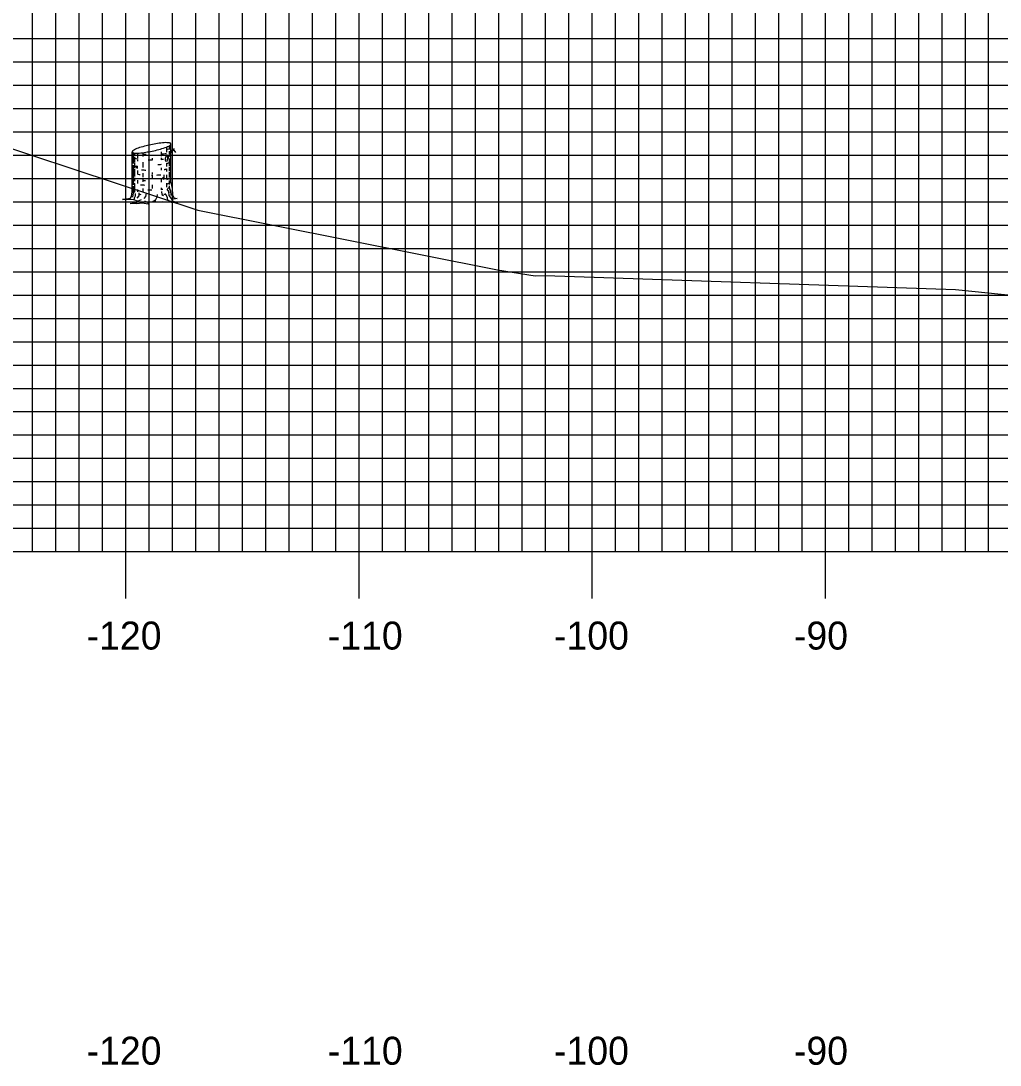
# Model space of a CAD drawing. Extents: x 857504 to 857847, y 364765 to 364985.
# Drawn here: x 857544.81 to 857586.8, y 364896.29 to 364941.06 of the extents above; entities that cross this region are included whole.
import ezdxf

# ---------------------------------------------------------------- set-up
doc = ezdxf.new("R2010")
doc.units = 0
for name, color, linetype in [('H_V ANNOTATION', 7, 'Continuous'), ('M_Trees_Conifer_Pay', 7, 'Continuous'), ('MAJOR', 7, 'Continuous'), ('MINOR', 7, 'Continuous'), ('S_Roadway_Centerline', 7, 'Continuous')]:
    doc.layers.add(name, color=color, linetype=linetype)

msp = doc.modelspace()

# ---------------------------------------------------------------- linework, layer by layer
at = {"layer": 'M_Trees_Conifer_Pay'}
for p, q in [((857551.056, 364935.645), (857551.056, 364935.422)), ((857551.173, 364935.706), (857551.173, 364935.544)), ((857551.245, 364934.132), (857551.245, 364935.779)), ((857549.58, 364933.721), (857549.58, 364935.443)), ((857549.628, 364935.406), (857549.628, 364934.935)), ((857549.686, 364935.395), (857549.686, 364935.297)), ((857549.686, 364935.223), (857549.686, 364935.019)), ((857549.811, 364935.387), (857549.811, 364935.155)), ((857550.031, 364935.407), (857550.031, 364935.239)), ((857550.827, 364935.449), (857550.827, 364935.25)), ((857550.827, 364935.192), (857550.827, 364935.103)), ((857551.056, 364935.334), (857551.056, 364935.286)), ((857551.173, 364935.476), (857551.173, 364935.348)), ((857549.628, 364934.87), (857549.628, 364934.562)), ((857549.686, 364934.961), (857549.686, 364934.761)), ((857549.811, 364935.114), (857549.811, 364935.04)), ((857550.031, 364935.002), (857550.031, 364934.765)), ((857550.437, 364935.176), (857550.437, 364935.08)), ((857550.827, 364934.756), (857550.827, 364934.651)), ((857551.056, 364934.951), (857551.056, 364934.819)), ((857551.113, 364935.151), (857551.061, 364935.091)), ((857551.173, 364935.161), (857551.173, 364934.825)), ((857551.173, 364934.788), (857551.173, 364934.626)), ((857549.628, 364934.515), (857549.628, 364934.023)), ((857549.686, 364934.714), (857549.686, 364934.378)), ((857549.686, 364934.325), (857549.686, 364934.189)), ((857549.811, 364934.636), (857549.811, 364934.498)), ((857550.031, 364934.521), (857550.031, 364934.368)), ((857550.031, 364934.325), (857550.031, 364934.152)), ((857550.437, 364934.562), (857550.437, 364934.488)), ((857550.437, 364934.463), (857550.437, 364934.315)), ((857551.056, 364934.708), (857551.056, 364934.599)), ((857551.056, 364934.463), (857551.056, 364934.321)), ((857551.173, 364934.578), (857551.173, 364934.362)), ((857551.173, 364934.331), (857551.173, 364934.257)), ((857549.628, 364933.969), (857549.628, 364933.721)), ((857549.686, 364934.09), (857549.686, 364933.712)), ((857549.811, 364934.226), (857549.811, 364934.084)), ((857550.031, 364933.874), (857550.031, 364933.721)), ((857550.437, 364934.023), (857550.437, 364933.87)), ((857550.827, 364934.284), (857550.827, 364934.137)), ((857550.827, 364933.905), (857550.827, 364933.817)), ((857551.056, 364934.094), (857551.056, 364933.922)), ((857551.173, 364934.216), (857551.173, 364934.043)), ((857549.811, 364933.822), (857549.811, 364933.728)), ((857549.811, 364933.328), (857549.974, 364933.392)), ((857550.248, 364933.264), (857550.122, 364933.328))]:
    msp.add_line(p, q, dxfattribs=at)
for points in [[(857551.028, 364935.239), (857550.997, 364935.155), (857550.993, 364935.087), (857551.024, 364935.023)], [(857551.061, 364935.277), (857551.098, 364935.202), (857551.145, 364935.259), (857551.203, 364935.328), (857551.296, 364935.521), (857551.36, 364935.569), (857551.391, 364935.575)], [(857551.076, 364935.023), (857551.113, 364935.151), (857551.176, 364935.266), (857551.207, 364935.334), (857551.276, 364935.48)], [(857551.29, 364935.509), (857551.366, 364935.517), (857551.438, 364935.418)], [(857549.76, 364934.749), (857549.754, 364934.844), (857549.797, 364934.821), (857549.797, 364934.727)], [(857550.899, 364934.35), (857550.911, 364934.273), (857550.958, 364934.284), (857550.946, 364934.45)], [(857551.245, 364934.132), (857551.296, 364933.87), (857551.312, 364933.596), (857551.37, 364933.471), (857551.506, 364933.44), (857551.275, 364933.403), (857551.275, 364933.403), (857551.281, 364933.355), (857551.529, 364933.261), (857551.254, 364933.277), (857550.899, 364933.298), (857550.577, 364933.287), (857550.584, 364933.37), (857550.435, 364933.287), (857550.248, 364933.264), (857550.273, 364933.197), (857550.005, 364933.24), (857549.785, 364933.213), (857549.492, 364933.23), (857549.781, 364933.287), (857549.811, 364933.328), (857549.649, 364933.386), (857549.412, 364933.397), (857549.171, 364933.397), (857549.513, 364933.454), (857549.554, 364933.534), (857549.58, 364933.721)], [(857551.071, 364933.843), (857551.145, 364933.738), (857551.15, 364933.565), (857551.275, 364933.403)], [(857551.17, 364933.989), (857551.176, 364933.843), (857551.224, 364933.775), (857551.234, 364933.576)], [(857549.628, 364933.674), (857549.607, 364933.596), (857549.587, 364933.502)], [(857549.706, 364933.654), (857549.712, 364933.538), (857549.659, 364933.45), (857549.649, 364933.386)], [(857549.869, 364933.681), (857549.869, 364933.549), (857549.781, 364933.45)], [(857550.096, 364933.44), (857550.163, 364933.534), (857550.19, 364933.674)], [(857550.584, 364933.37), (857550.658, 364933.511), (857550.668, 364933.613)], [(857550.834, 364933.738), (857550.845, 364933.613), (857550.919, 364933.569)], [(857551.113, 364933.349), (857551.098, 364933.487), (857551.024, 364933.616)]]:
    msp.add_lwpolyline(points, dxfattribs=at)
for centre, radius, start, end in [((857551.436, 364930.676), 5.179, 101.7194, 108.0594), ((857551.436, 364930.676), 5.179, 95.3794, 101.7194), ((857551.026, 364935.034), 0.802, 79.2194, 95.3794), ((857550.746, 364936.384), 0.802, 288.0594, 304.2194), ((857551.129, 364935.575), 0.251, 71.0501, 79.2194), ((857551.056, 364935.929), 0.251, 304.2194, 312.3887), ((857551.184, 364935.735), 0.0817, 56.7194, 71.0501), ((857551.169, 364935.804), 0.0817, 312.3887, 326.7194), ((857551.185, 364935.664), 0.0624, 311.2506, 330), ((857551.2, 364935.759), 0.0527, 46.923, 56.7194), ((857551.214, 364935.774), 0.0314, 34.2194, 46.923), ((857551.194, 364935.788), 0.0527, 326.7194, 336.5158), ((857551.201, 364935.655), 0.0441, 330, 343.9485), ((857551.218, 364935.777), 0.0264, 23.4074, 34.2194), ((857551.213, 364935.78), 0.0314, 336.5158, 349.2194), ((857551.222, 364935.779), 0.0226, 11.7194, 23.4074), ((857551.211, 364935.652), 0.0334, 343.9485, 354.2151), ((857551.222, 364935.779), 0.0226, 0.0315, 11.7194), ((857551.218, 364935.779), 0.0264, 349.2194, 0.0315), ((857549.613, 364935.265), 0.0334, 163.9485, 180), ((857549.613, 364935.265), 0.0334, 180, 196.0515), ((857549.612, 364935.442), 0.0314, 156.5158, 169.2194), ((857549.607, 364935.443), 0.0264, 169.2194, 180.0315), ((857549.603, 364935.443), 0.0226, 180.0315, 191.7194), ((857549.603, 364935.443), 0.0226, 191.7194, 203.4074), ((857549.623, 364935.268), 0.0441, 196.0515, 210), ((857549.607, 364935.444), 0.0264, 203.4074, 214.2194), ((857549.631, 364935.434), 0.0527, 146.7194, 156.5158), ((857549.611, 364935.447), 0.0314, 214.2194, 226.923), ((857549.639, 364935.277), 0.0624, 210, 228.7494), ((857549.656, 364935.418), 0.0817, 132.3887, 146.7194), ((857549.625, 364935.463), 0.0527, 226.923, 236.7194), ((857549.641, 364935.487), 0.0817, 236.7194, 251.0501), ((857549.711, 364935.36), 0.172, 228.7494, 240), ((857549.77, 364935.293), 0.251, 124.2194, 132.3887), ((857549.696, 364935.647), 0.251, 251.0501, 259.2194), ((857549.91, 364935.705), 0.571, 240, 240.3367), ((857550.079, 364934.837), 0.802, 108.0594, 124.2194), ((857549.799, 364936.188), 0.802, 259.2194, 275.3794), ((857549.389, 364940.546), 5.179, 275.3794, 281.7194), ((857550.413, 364939.455), 4.124, 264.6955, 266.7331), ((857549.389, 364940.546), 5.179, 281.7194, 288.0594), ((857550.413, 364939.455), 4.124, 276.238, 278.1032), ((857550.914, 364935.938), 0.571, 278.1032, 284.3667), ((857550.914, 364936.092), 0.571, 284.4317, 292.4132), ((857550.914, 364935.938), 0.571, 297.0237, 300), ((857551.113, 364935.747), 0.172, 300, 311.2506), ((857551.113, 364935.593), 0.172, 300, 311.2506), ((857551.185, 364935.51), 0.0624, 311.2506, 330), ((857551.201, 364935.501), 0.0441, 330, 343.9485), ((857551.211, 364935.498), 0.0334, 343.9485, 354.2151), ((857549.613, 364934.818), 0.0334, 163.9485, 180), ((857549.613, 364934.818), 0.0334, 180, 196.0515), ((857549.623, 364934.821), 0.0441, 196.0515, 210), ((857549.639, 364934.83), 0.0624, 210, 228.7494), ((857549.711, 364934.913), 0.172, 228.7494, 240), ((857549.91, 364935.258), 0.571, 240, 240.3367), ((857549.912, 364935.494), 0.571, 240, 247.0587), ((857549.91, 364935.705), 0.571, 246.8597, 257.9846), ((857550.411, 364939.222), 4.124, 268.0751, 270), ((857550.411, 364939.222), 4.124, 270, 270.3581), ((857550.413, 364939.011), 4.124, 273.7052, 275.9504), ((857550.411, 364939.222), 4.124, 275.7849, 277.0558), ((857550.913, 364935.494), 0.571, 284.4493, 297.0429), ((857550.912, 364935.258), 0.571, 297.1896, 300), ((857551.111, 364934.913), 0.172, 300, 311.2506), ((857551.184, 364934.83), 0.0624, 311.2506, 330), ((857551.2, 364934.821), 0.0441, 330, 343.9485), ((857551.21, 364934.818), 0.0334, 343.9485, 354.2151), ((857551.211, 364935.054), 0.0334, 343.9485, 354.2151), ((857549.613, 364934.608), 0.0334, 163.9485, 180), ((857549.613, 364934.608), 0.0334, 180, 196.0515), ((857549.613, 364934.371), 0.0334, 163.9485, 180), ((857549.613, 364934.371), 0.0334, 180, 196.0515), ((857549.623, 364934.611), 0.0441, 196.0515, 210), ((857549.623, 364934.374), 0.0441, 196.0515, 210), ((857549.639, 364934.62), 0.0624, 210, 228.7494), ((857549.639, 364934.383), 0.0624, 210, 228.7494), ((857549.711, 364934.703), 0.172, 228.7494, 240), ((857549.711, 364934.466), 0.172, 228.7494, 240), ((857549.91, 364935.048), 0.571, 240, 246.8597), ((857549.91, 364934.811), 0.571, 240, 246.8597), ((857549.91, 364935.048), 0.571, 259.2707, 261.8968), ((857550.411, 364938.565), 4.124, 261.8968, 263.1474), ((857550.411, 364938.775), 4.124, 264.081, 266.6676), ((857550.411, 364938.565), 4.124, 270, 270.3581), ((857550.411, 364938.565), 4.124, 273.1493, 275.4569), ((857550.411, 364938.775), 4.124, 277.6125, 278.1032), ((857550.912, 364935.258), 0.571, 278.1032, 286.9296), ((857550.912, 364934.811), 0.571, 285.3983, 297.1896), ((857550.912, 364935.048), 0.571, 297.1896, 300), ((857551.111, 364934.703), 0.172, 300, 311.2506), ((857551.184, 364934.62), 0.0624, 311.2506, 330), ((857551.2, 364934.611), 0.0441, 330, 343.9485), ((857551.21, 364934.608), 0.0334, 343.9485, 354.2151), ((857549.613, 364934.174), 0.0334, 163.9485, 180), ((857549.613, 364933.978), 0.0334, 163.9485, 180), ((857549.613, 364933.978), 0.0334, 180, 196.0515), ((857549.623, 364933.981), 0.0441, 196.0515, 210), ((857549.639, 364933.99), 0.0624, 210, 228.7494), ((857549.711, 364934.073), 0.172, 228.7494, 240), ((857549.9, 364934.62), 0.571, 241.2369, 248.0268), ((857549.91, 364934.418), 0.571, 240, 246.8597), ((857550.411, 364938.131), 4.124, 263.4991, 265.8397), ((857550.411, 364938.329), 4.124, 264.716, 266.3193), ((857550.411, 364937.935), 4.124, 275.7849, 276.7896), ((857550.912, 364934.418), 0.571, 288.5067, 297.2721), ((857550.912, 364934.613), 0.571, 289.2907, 300), ((857551.111, 364934.268), 0.172, 300, 311.2506), ((857551.184, 364934.186), 0.0624, 311.2506, 330), ((857551.2, 364934.177), 0.0441, 330, 343.9485), ((857551.21, 364934.174), 0.0334, 343.9485, 354.2151), ((857549.613, 364933.758), 0.0334, 163.9485, 180), ((857549.613, 364933.758), 0.0334, 180, 196.0515), ((857549.623, 364933.761), 0.0441, 196.0515, 210), ((857549.639, 364933.77), 0.0624, 210, 228.7494), ((857549.711, 364933.853), 0.172, 228.7494, 240), ((857549.91, 364934.198), 0.571, 240, 244.5314), ((857550.411, 364937.715), 4.124, 262.4438, 263.512), ((857550.411, 364937.935), 4.124, 267.8117, 270), ((857550.411, 364937.935), 4.124, 270, 270.1328), ((857550.411, 364937.715), 4.124, 277.3684, 278.1032), ((857550.912, 364934.198), 0.571, 278.1032, 281.637), ((857551.111, 364933.853), 0.172, 300, 311.2506), ((857551.184, 364933.77), 0.0624, 311.2506, 330), ((857551.2, 364933.761), 0.0441, 330, 343.9485), ((857551.21, 364933.758), 0.0334, 343.9485, 354.2151)]:
    msp.add_arc(centre, radius, start, end, dxfattribs=at)
at = {"layer": 'MAJOR'}
for p, q in [((857549.308, 364918.302), (857549.308, 364963.302)), ((857559.308, 364918.302), (857559.308, 364963.302)), ((857569.308, 364918.302), (857569.308, 364963.302)), ((857579.308, 364918.302), (857579.308, 364963.302)), ((857529.308, 364938.302), (857809.308, 364938.302)), ((857529.308, 364933.302), (857809.308, 364933.302)), ((857529.308, 364928.302), (857809.308, 364928.302)), ((857529.308, 364923.302), (857809.308, 364923.302)), ((857529.308, 364918.302), (857809.308, 364918.302)), ((857529.308, 364918.302), (857809.308, 364918.302)), ((857549.308, 364916.298), (857549.308, 364918.302)), ((857559.308, 364916.298), (857559.308, 364918.302)), ((857569.308, 364916.298), (857569.308, 364918.302)), ((857579.308, 364916.298), (857579.308, 364918.302))]:
    msp.add_line(p, q, dxfattribs=at)
at = {"layer": 'MINOR'}
for p, q in [((857545.308, 364918.302), (857545.308, 364963.302)), ((857546.308, 364918.302), (857546.308, 364963.302)), ((857547.308, 364918.302), (857547.308, 364963.302)), ((857548.308, 364918.302), (857548.308, 364963.302)), ((857550.308, 364918.302), (857550.308, 364963.302)), ((857551.308, 364918.302), (857551.308, 364963.302)), ((857552.308, 364918.302), (857552.308, 364963.302)), ((857553.308, 364918.302), (857553.308, 364963.302)), ((857554.308, 364918.302), (857554.308, 364963.302)), ((857555.308, 364918.302), (857555.308, 364963.302)), ((857556.308, 364918.302), (857556.308, 364963.302)), ((857557.308, 364918.302), (857557.308, 364963.302)), ((857558.308, 364918.302), (857558.308, 364963.302)), ((857560.308, 364918.302), (857560.308, 364963.302)), ((857561.308, 364918.302), (857561.308, 364963.302)), ((857562.308, 364918.302), (857562.308, 364963.302)), ((857563.308, 364918.302), (857563.308, 364963.302)), ((857564.308, 364918.302), (857564.308, 364963.302)), ((857565.308, 364918.302), (857565.308, 364963.302)), ((857566.308, 364918.302), (857566.308, 364963.302)), ((857567.308, 364918.302), (857567.308, 364963.302)), ((857568.308, 364918.302), (857568.308, 364963.302)), ((857570.308, 364918.302), (857570.308, 364963.302)), ((857571.308, 364918.302), (857571.308, 364963.302)), ((857572.308, 364918.302), (857572.308, 364963.302)), ((857573.308, 364918.302), (857573.308, 364963.302)), ((857574.308, 364918.302), (857574.308, 364963.302)), ((857575.308, 364918.302), (857575.308, 364963.302)), ((857576.308, 364918.302), (857576.308, 364963.302)), ((857577.308, 364918.302), (857577.308, 364963.302)), ((857578.308, 364918.302), (857578.308, 364963.302)), ((857580.308, 364918.302), (857580.308, 364963.302)), ((857581.308, 364918.302), (857581.308, 364963.302)), ((857582.308, 364918.302), (857582.308, 364963.302)), ((857583.308, 364918.302), (857583.308, 364963.302)), ((857584.308, 364918.302), (857584.308, 364963.302)), ((857585.308, 364918.302), (857585.308, 364963.302)), ((857586.308, 364918.302), (857586.308, 364963.302)), ((857529.308, 364940.302), (857809.308, 364940.302)), ((857529.308, 364939.302), (857809.308, 364939.302)), ((857529.308, 364937.302), (857809.308, 364937.302)), ((857529.308, 364936.302), (857809.308, 364936.302)), ((857529.308, 364935.302), (857809.308, 364935.302)), ((857529.308, 364934.302), (857809.308, 364934.302)), ((857529.308, 364932.302), (857809.308, 364932.302)), ((857529.308, 364931.302), (857809.308, 364931.302)), ((857529.308, 364930.302), (857809.308, 364930.302)), ((857529.308, 364929.302), (857809.308, 364929.302)), ((857529.308, 364927.302), (857809.308, 364927.302)), ((857529.308, 364926.302), (857809.308, 364926.302)), ((857529.308, 364925.302), (857809.308, 364925.302)), ((857529.308, 364924.302), (857809.308, 364924.302)), ((857529.308, 364922.302), (857809.308, 364922.302)), ((857529.308, 364921.302), (857809.308, 364921.302)), ((857529.308, 364920.302), (857809.308, 364920.302)), ((857529.308, 364919.302), (857809.308, 364919.302))]:
    msp.add_line(p, q, dxfattribs=at)
at = {"layer": 'S_Roadway_Centerline'}
msp.add_lwpolyline([(857529.308, 364940.811), (857535.655, 364938.647), (857539.931, 364937.059), (857552.4, 364932.939), (857565.242, 364930.376), (857566.855, 364930.129), (857567.294, 364930.134), (857584.882, 364929.536), (857589.507, 364929.07)], dxfattribs=at)

# ---------------------------------------------------------------- texts
at = {"layer": 'H_V ANNOTATION'}
for s, p in [('-120', (857547.627, 364914.102)), ('-110', (857557.97, 364914.102)), ('-100', (857567.67, 364914.102)), ('-90', (857577.959, 364914.102)), ('-120', (857547.627, 364896.302)), ('-110', (857557.97, 364896.302)), ('-100', (857567.67, 364896.302)), ('-90', (857577.959, 364896.302))]:
    msp.add_text(s, height=1.2, dxfattribs=at).set_placement(p)

doc.saveas('drawing.dxf')
